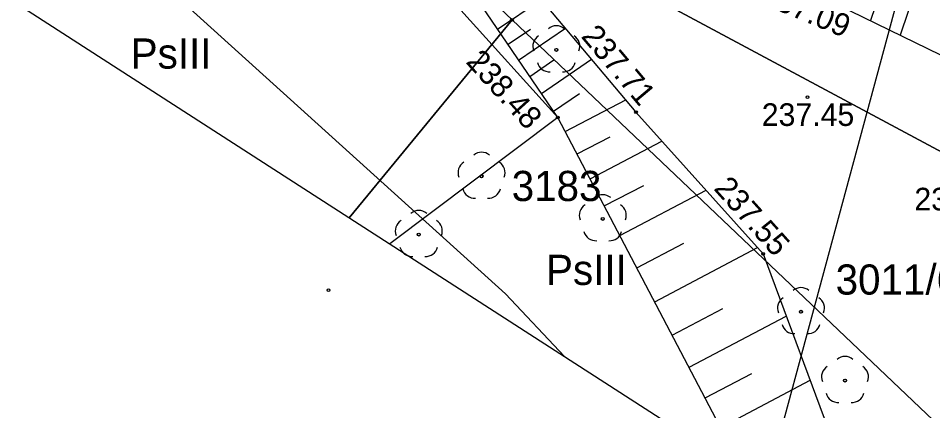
# Model space of a CAD drawing. Extents: x 6596400 to 6597200, y 5539751 to 5540251.
# Drawn here: x 6596673.62 to 6596703.94, y 5540079.07 to 5540092.08 of the extents above; entities that cross this region are included whole.
import ezdxf

# ---------------------------------------------------------------- set-up
doc = ezdxf.new("R2010")
doc.units = 0
for name, color, linetype in [('000 Inne (niezydentyfikowane)', 7, 'Continuous'), ('140-Punkty robocze', 7, 'Continuous'), ('203-punkt graniczny', 7, 'Continuous'), ('209-oznaczenie konturu klasyfikacyjnego', 7, 'Continuous'), ('211-numer działki ewidencyjnej', 7, 'Continuous'), ('217-kontur klasyfikacyjny', 7, 'Continuous'), ('218-kontur użytku gruntowego', 7, 'Continuous'), ('219-działka ewidencyjna', 7, 'Continuous'), ('drzewo liściaste', 7, 'Continuous'), ('Linia obszaru zagospodarowania terenu', 7, 'Continuous'), ('ogrodzenie trwałe', 7, 'Continuous'), ('pikieta sztuczna', 7, 'Continuous'), ('pikieta sztuczna-Atr2', 7, 'Continuous'), ('skarpa nieumocniona', 7, 'Continuous'), ('Strefa korytarza ekologicznego', 7, 'Continuous'), ('Zakres', 7, 'Continuous')]:
    doc.layers.add(name, color=color, linetype=linetype)

# ---------------------------------------------------------------- blocks, each defined once
blk = doc.blocks.new('203')
blk.add_circle((0, 0), 0.045)
blk = doc.blocks.new('OP021')
blk.add_circle((0, 0), 0.05)
for centre, start, end in [((0, 0.4), 49.272, 130.728), ((-0.38, 0.124), 121.308, 202.548), ((0.38, 0.124), 337.452, 58.692), ((-0.235, -0.324), 193.221, 274.871), ((0.235, -0.324), 265.129, 346.779)]:
    blk.add_arc(centre, 0.4, start, end)
blk = doc.blocks.new('PW01')
blk.add_circle((0, 0), 0.045)
blk = doc.blocks.new('PIKIETA')
blk.add_circle((0, 0), 0.045)

msp = doc.modelspace()

# ---------------------------------------------------------------- linework, layer by layer
at = {"layer": '000 Inne (niezydentyfikowane)'}
for p, q in [((6596689.51, 5540091.72), (6596690.96, 5540092.7)), ((6596690.21, 5540090.69), (6596691.76, 5540091.75)), ((6596689.86, 5540091.22), (6596690.6, 5540091.72)), ((6596690.58, 5540090.15), (6596691.38, 5540090.7)), ((6596690.97, 5540089.59), (6596692.63, 5540090.72)), ((6596691.37, 5540089), (6596692.23, 5540089.59)), ((6596691.75, 5540088.33), (6596693.76, 5540089.38)), ((6596692.15, 5540087.58), (6596693.24, 5540088.15)), ((6596692.58, 5540086.76), (6596694.96, 5540088.01)), ((6596693.05, 5540085.86), (6596694.36, 5540086.54)), ((6596693.57, 5540084.88), (6596696.43, 5540086.38)), ((6596694.13, 5540083.81), (6596695.69, 5540084.63)), ((6596694.72, 5540082.68), (6596698.13, 5540084.48)), ((6596695.3, 5540081.58), (6596696.98, 5540082.46)), ((6596695.86, 5540080.51), (6596699.08, 5540082.21)), ((6596696.39, 5540079.5), (6596697.94, 5540080.31)), ((6596696.91, 5540078.52), (6596699.88, 5540080.08))]:
    msp.add_line(p, q, dxfattribs=at)
for points in [[(6596702.35, 5540093.41), (6596701.88, 5540092)], [(6596703.38, 5540093.07), (6596702.86, 5540091.52)]]:
    msp.add_lwpolyline(points, dxfattribs=at)
at = {"layer": '217-kontur klasyfikacyjny'}
for points in [[(6596689.99, 5540092.03), (6596682.08, 5540099.52)], [(6596689.99, 5540092.03), (6596684.59, 5540085.468)], [(6596684.59, 5540085.468), (6596689.99, 5540092.03)], [(6596710.04, 5540072.97), (6596689.99, 5540092.03)]]:
    msp.add_lwpolyline(points, dxfattribs=at)
at = {"layer": '218-kontur użytku gruntowego'}
for points in [[(6596689.99, 5540092.03), (6596682.08, 5540099.52)], [(6596682.08, 5540099.52), (6596689.99, 5540092.03)], [(6596712.64, 5540083.14), (6596682.08, 5540099.52)], [(6596682.08, 5540099.52), (6596712.64, 5540083.14)], [(6596689.99, 5540092.03), (6596684.59, 5540085.468)], [(6596684.59, 5540085.468), (6596689.99, 5540092.03)], [(6596710.04, 5540072.97), (6596689.99, 5540092.03)], [(6596689.99, 5540092.03), (6596710.04, 5540072.97)]]:
    msp.add_lwpolyline(points, dxfattribs=at)
at = {"layer": '219-działka ewidencyjna'}
for points in [[(6596712.64, 5540083.14), (6596682.08, 5540099.52)], [(6596689.99, 5540092.03), (6596682.08, 5540099.52)], [(6596684.59, 5540085.468), (6596689.99, 5540092.03)], [(6596710.04, 5540072.97), (6596689.99, 5540092.03)]]:
    msp.add_lwpolyline(points, dxfattribs=at)
at = {"layer": 'Linia obszaru zagospodarowania terenu'}
msp.add_lwpolyline([(6596649.353, 5540112.883), (6596665.77, 5540102.07), (6596672.77, 5540097.71), (6596678.05, 5540093.55), (6596689.77, 5540082.95), (6596691.734, 5540080.864)], dxfattribs=at)
at = {"layer": 'ogrodzenie trwałe'}
msp.add_lwpolyline([(6596667.03, 5540110.64), (6596668.29, 5540109.72), (6596674.46, 5540105.01), (6596681.86, 5540099.47), (6596691.51, 5540088.79), (6596685.94, 5540084.598)], dxfattribs=at)
at = {"layer": 'skarpa nieumocniona'}
for points in [[(6596678.95, 5540103.44), (6596684.48, 5540100.39), (6596690.52, 5540096.75), (6596701.2, 5540092.33), (6596705.49, 5540090.24), (6596709.93, 5540088.59), (6596713.91, 5540088.19), (6596713.79, 5540089.29), (6596710.4, 5540090.34), (6596706.06, 5540092.18), (6596701.79, 5540093.6), (6596690.99, 5540097.77), (6596684.6, 5540101.39), (6596679.33, 5540104.04), (6596675.06, 5540106.16)], [(6596678.95, 5540103.44), (6596684.48, 5540100.39), (6596690.52, 5540096.75), (6596701.2, 5540092.33), (6596705.49, 5540090.24), (6596709.93, 5540088.59), (6596713.91, 5540088.19), (6596713.79, 5540089.29), (6596710.4, 5540090.34), (6596706.06, 5540092.18), (6596701.79, 5540093.6), (6596690.99, 5540097.77), (6596684.6, 5540101.39), (6596679.33, 5540104.04), (6596675.06, 5540106.16)], [(6596678.95, 5540103.44), (6596684.48, 5540100.39), (6596694.1, 5540088.97), (6596698.32, 5540084.27), (6596700.74, 5540077.75), (6596705.03, 5540070.97), (6596697.73, 5540077), (6596697.69, 5540077.02), (6596691.51, 5540088.79), (6596684.27, 5540099.42), (6596679.14, 5540103.03), (6596675.06, 5540106.16)], [(6596678.95, 5540103.44), (6596684.48, 5540100.39), (6596694.1, 5540088.97), (6596698.32, 5540084.27), (6596700.74, 5540077.75), (6596705.03, 5540070.97), (6596697.73, 5540077), (6596697.69, 5540077.02), (6596691.51, 5540088.79), (6596684.27, 5540099.42), (6596679.14, 5540103.03), (6596675.06, 5540106.16)]]:
    msp.add_lwpolyline(points, close=True, dxfattribs=at)
at = {"layer": 'Strefa korytarza ekologicznego'}
msp.add_lwpolyline([(6596698.383, 5540076.46), (6596706.03, 5540104.75), (6596710.01, 5540120.89)], dxfattribs=at)
at = {"layer": 'Zakres'}
msp.add_lwpolyline([(6596822.22, 5540097.5), (6596800.39, 5540105.4), (6596755.76, 5540121.45), (6596697.73, 5540120.74), (6596659.35, 5540133.92), (6596647.64, 5540109.28), (6596697.73, 5540077), (6596721.01, 5540057.77), (6596727.72, 5540045.95), (6596731.95, 5540033.61), (6596741.17, 5540031.18), (6596755.59, 5540029.2), (6596757.85, 5540044.22), (6596787.25, 5540055.04), (6596806.3, 5540048.33), (6596813.97, 5540042.6), (6596833.15, 5540068.58), (6596822.3, 5540077.75)], close=True, dxfattribs=at)

# ---------------------------------------------------------------- block references
at = {"layer": '140-Punkty robocze'}
for p in [(6596691.46, 5540091.03), (6596688.98, 5540086.84), (6596693, 5540085.43), (6596686.9, 5540084.91), (6596683.91, 5540083.07), (6596699.57, 5540082.35), (6596701.03, 5540080.07)]:
    msp.add_blockref('PIKIETA', p, dxfattribs=at)
at = {"layer": '203-punkt graniczny'}
msp.add_blockref('203', (6596689.99, 5540092.03), dxfattribs=at)
at = {"layer": 'drzewo liściaste'}
for p in [(6596691.46, 5540091.03), (6596688.98, 5540086.84), (6596693, 5540085.43), (6596686.9, 5540084.91), (6596699.57, 5540082.35), (6596701.03, 5540080.07)]:
    msp.add_blockref('OP021', p, dxfattribs=at)
at = {"layer": 'pikieta sztuczna'}
for p in [(6596699.79, 5540089.46), (6596691.51, 5540088.79), (6596694.1, 5540088.97), (6596698.32, 5540084.27)]:
    msp.add_blockref('PW01', p, dxfattribs=at)

# ---------------------------------------------------------------- texts
at = {"layer": '209-oznaczenie konturu klasyfikacyjnego'}
for p in [(6596677.35, 5540090.41), (6596691.12, 5540083.24)]:
    msp.add_text('PsIII', height=1, dxfattribs=at).set_placement(p)
at = {"layer": '211-numer działki ewidencyjnej'}
for s, p in [('3183', (6596689.98, 5540086.02)), ('3011/6', (6596700.72, 5540082.92))]:
    msp.add_text(s, height=1, dxfattribs=at).set_placement(p)
at = {"layer": 'pikieta sztuczna-Atr2'}
for s, rotation, p in [('237.09', 337.517, (6596698.173, 5540092.597)), ('237.71', 310.11, (6596692.256, 5540091.467)), ('238.48', 312.1, (6596688.434, 5540090.617)), ('237.55', 311.92, (6596696.652, 5540086.419))]:
    msp.add_text(s, height=0.75, rotation=rotation, dxfattribs=at).set_placement(p)
for s, p in [('237.45', (6596698.27, 5540088.51)), ('236.87', (6596703.33, 5540085.71))]:
    msp.add_text(s, height=0.75, dxfattribs=at).set_placement(p)

doc.saveas('drawing.dxf')
